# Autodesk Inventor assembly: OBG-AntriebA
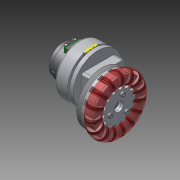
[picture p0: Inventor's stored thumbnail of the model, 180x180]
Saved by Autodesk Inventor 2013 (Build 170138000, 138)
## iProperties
Created: 2012-07
Part Number: OBG-AntriebA
Document SubType Name: Assembly
Designer: rYan
Mass: 197.276 g
Surface Area: 535.324 cm^2
Volume: 71.3862 cm^3
Density: 2.76351 g/cm^3
Author: rYan
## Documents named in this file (8)
- D:\SVN\2013\Inventor\Antrieb\OBG-AntriebA.iam
- D:\SVN\2013\Inventor\Antrieb\LagerbockA.ipt
- D:\SVN\2013\Inventor\Kaufteile\MaxonEC45-30W.ipt
- D:\SVN\2013\Inventor\Kaufteile\Ritzel z15.ipt
- D:\SVN\2013\Inventor\Antrieb\UBG-Rad.iam
- D:\SVN\2013\Inventor\Antrieb\Encoderhalter.ipt
- D:\SVN\2013\Inventor\Kaufteile\E8P-X-157-S-D-M-X\E8P-X-157-S-D-M-X.iam
- D:\SVN\2013\Inventor\Inhaltscenter\de-DE\DIN 7984\DIN 7984 - M3 x 8.ipt
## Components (9 placed, 7 different names)
1. LagerbockA:1 — Passend:3, Winkel:1, Passend:16, Passend:17, Passend:19, Passend:20, Passend:21
2. MaxonEC45-30W:1 — Passend:3, Passend:15, Passend:20, Passend:21, Passend:22, Fluchtend:1, Passend:23
3. Ritzel Z=15:1 — Passend:22, Fluchtend:1
4. UBG-Rad:1 [sub-assembly] — Passend:16, Passend:17
5. Encoderhalter:1 — Passend:12, Passend:13, Passend:14, Passend:15, Winkel:1, Passend:23
6. E8P-X-157-S-D-M-X:1 [sub-assembly] — Passend:12, Passend:13, Passend:14
7. DIN 7984 M3 x 8:1 — Passend:19
8. DIN 7984 M3 x 8:2
9. DIN 7984 M3 x 8:3
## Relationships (14: Mate 12, Angle 1, Flush 1)
- Passend:3 [Mate]: LagerbockA:1 ↔ MaxonEC45-30W:1
- Passend:12 [Mate]: Encoderhalter:1 ↔ E8P-X-157-S-D-M-X:1
- Passend:13 [Mate]: Encoderhalter:1 ↔ E8P-X-157-S-D-M-X:1
- Passend:14 [Mate]: Encoderhalter:1 ↔ E8P-X-157-S-D-M-X:1
- Passend:15 [Mate]: MaxonEC45-30W:1 ↔ Encoderhalter:1
- Winkel:1 [Angle]: LagerbockA:1 ↔ Encoderhalter:1
- Passend:16 [Mate]: LagerbockA:1 ↔ UBG-Rad:1
- Passend:17 [Mate]: LagerbockA:1 ↔ UBG-Rad:1
- Passend:19 [Mate]: LagerbockA:1 ↔ DIN 7984 M3 x 8:1
- Passend:20 [Mate]: LagerbockA:1 ↔ MaxonEC45-30W:1
- Passend:21 [Mate]: LagerbockA:1 ↔ MaxonEC45-30W:1
- Passend:22 [Mate]: MaxonEC45-30W:1 ↔ Ritzel Z=15:1
- Fluchtend:1 [Flush]: MaxonEC45-30W:1 ↔ Ritzel Z=15:1
- Passend:23 [Mate]: MaxonEC45-30W:1 ↔ Encoderhalter:1
